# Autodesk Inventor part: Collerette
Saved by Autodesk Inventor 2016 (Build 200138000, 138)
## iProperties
Created: 2013-08
Part Number: Collerette
Material: Générique
Document SubType Name: Modeling
Designer: hilarion
Density: 1 g/cm^3
Appearance: Par défaut
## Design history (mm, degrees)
node "Collerette1"
node "Collerette"
node "Base1"
